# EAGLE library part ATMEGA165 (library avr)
MICROCONTROLLER 16 Kbytes FLASH 1 Kbytes SRAM 512 bytes EEPROM USART 8-channel 10 bit ADC USI
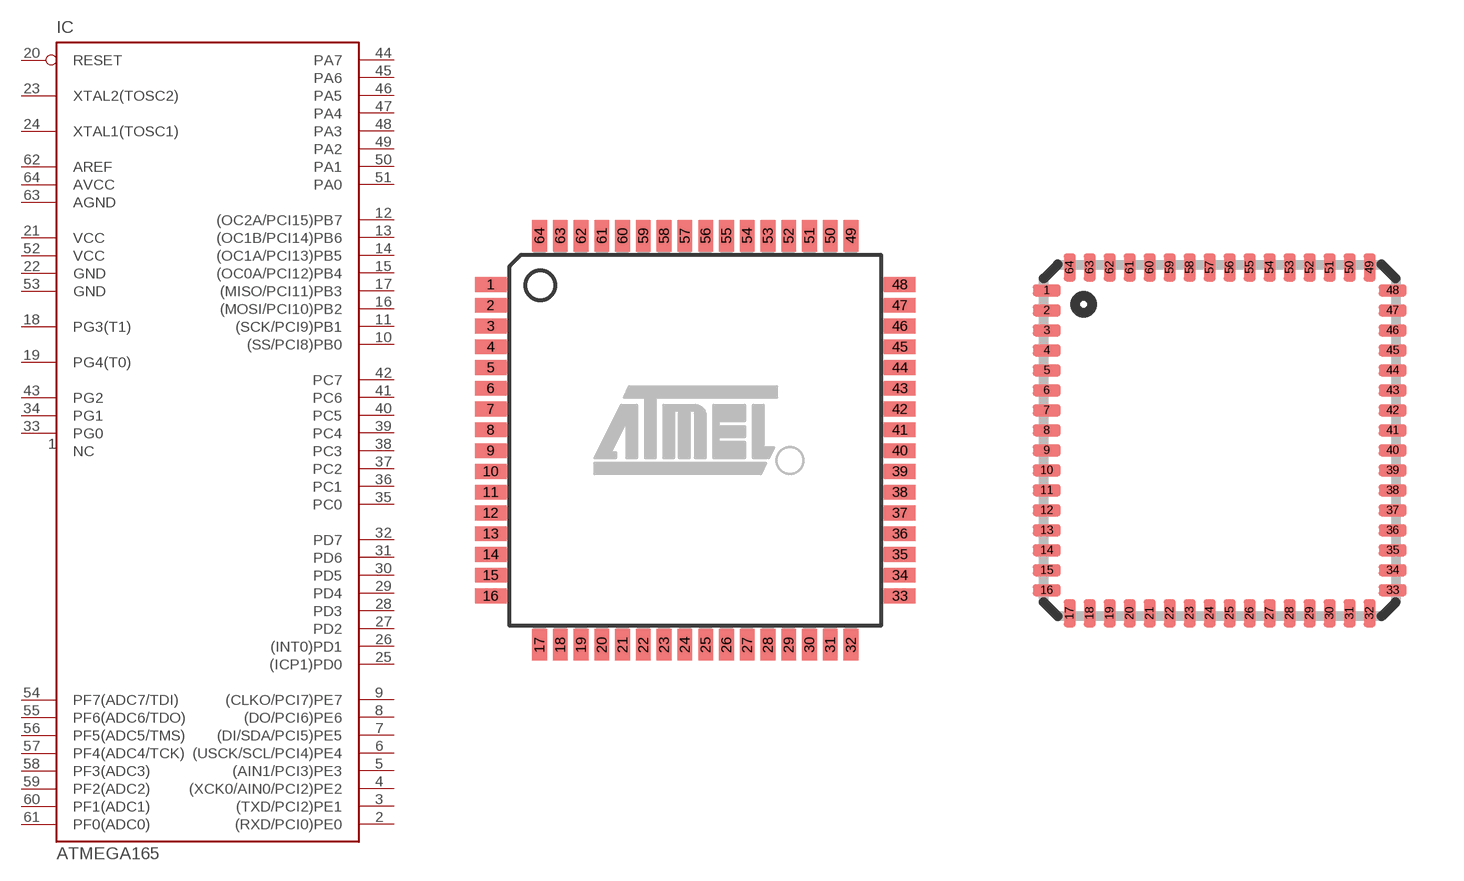
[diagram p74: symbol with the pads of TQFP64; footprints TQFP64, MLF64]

Designator prefix IC

## ATMEGA165-16A, ATMEGA165V-8A  [TQFP64]
1  NC  nc
2  (RXD/PCI0)PE0
3  (TXD/PCI2)PE1
4  (XCK0/AIN0/PCI2)PE2
5  (AIN1/PCI3)PE3
6  (USCK/SCL/PCI4)PE4
7  (DI/SDA/PCI5)PE5
8  (DO/PCI6)PE6
9  (CLKO/PCI7)PE7
10  (SS/PCI8)PB0
11  (SCK/PCI9)PB1
12  (OC2A/PCI15)PB7
13  (OC1B/PCI14)PB6
14  (OC1A/PCI13)PB5
15  (OC0A/PCI12)PB4
16  (MOSI/PCI10)PB2
17  (MISO/PCI11)PB3
18  PG3(T1)
19  PG4(T0)
20  RESET  in
21  VCC  pwr
22  GND  pwr
23  XTAL2(TOSC2)
24  XTAL1(TOSC1)
25  (ICP1)PD0
26  (INT0)PD1
27  PD2
28  PD3
29  PD4
30  PD5
31  PD6
32  PD7
33  PG0
34  PG1
35  PC0
36  PC1
37  PC2
38  PC3
39  PC4
40  PC5
41  PC6
42  PC7
43  PG2
44  PA7
45  PA6
46  PA5
47  PA4
48  PA3
49  PA2
50  PA1
51  PA0
52  VCC  pwr
53  GND  pwr
54  PF7(ADC7/TDI)  in
55  PF6(ADC6/TDO)  in
56  PF5(ADC5/TMS)  in
57  PF4(ADC4/TCK)  in
58  PF3(ADC3)  in
59  PF2(ADC2)  in
60  PF1(ADC1)  in
61  PF0(ADC0)  in
62  AREF  pwr
63  AGND  pwr
64  AVCC  pwr

## ATMEGA165-16M, ATMEGA165V-8M  [MLF64]
Pads as for TQFP64

## Footprint TQFP64 (pad centres in mm)
Thin Plasic Quad Flat Package
smd 1.194 x 0.559: 1 -7.76,5.905; 2 -7.76,5.118; 3 -7.76,4.331; 4 -7.76,3.543; 5 -7.76,2.756; 6 -7.76,1.968; 7 -7.76,1.181; 8 -7.76,0.394; 9 -7.76,-0.394; 10 -7.76,-1.181; 11 -7.76,-1.968; 12 -7.76,-2.756; 13 -7.76,-3.543; 14 -7.76,-4.331; 15 -7.76,-5.118; 16 -7.76,-5.905; 33 7.76,-5.905; 34 7.76,-5.118; 35 7.76,-4.331; 36 7.76,-3.543; 37 7.76,-2.756; 38 7.76,-1.968; 39 7.76,-1.181; 40 7.76,-0.394; 41 7.76,0.394; 42 7.76,1.181; 43 7.76,1.968; 44 7.76,2.756; 45 7.76,3.543; 46 7.76,4.331; 47 7.76,5.118; 48 7.76,5.905
smd 0.559 x 1.194: 17 -5.905,-7.76; 18 -5.118,-7.76; 19 -4.331,-7.76; 20 -3.543,-7.76; 21 -2.756,-7.76; 22 -1.968,-7.76; 23 -1.181,-7.76; 24 -0.394,-7.76; 25 0.394,-7.76; 26 1.181,-7.76; 27 1.968,-7.76; 28 2.756,-7.76; 29 3.543,-7.76; 30 4.331,-7.76; 31 5.118,-7.76; 32 5.905,-7.76; 49 5.905,7.76; 50 5.118,7.76; 51 4.331,7.76; 52 3.543,7.76; 53 2.756,7.76; 54 1.968,7.76; 55 1.181,7.76; 56 0.394,7.76; 57 -0.394,7.76; 58 -1.181,7.76; 59 -1.968,7.76; 60 -2.756,7.76; 61 -3.543,7.76; 62 -4.331,7.76; 63 -5.118,7.76; 64 -5.905,7.76

## Footprint MLF64 (pad centres in mm)
64M1 Micro Lead Frame package (MLF)
smd 0.7 x 0.3: 1 -4.325,3.75; 2 -4.325,3.25; 3 -4.325,2.75; 4 -4.325,2.25; 5 -4.325,1.75; 6 -4.325,1.25; 7 -4.325,0.75; 8 -4.325,0.25; 9 -4.325,-0.25; 10 -4.325,-0.75; 11 -4.325,-1.25; 12 -4.325,-1.75; 13 -4.325,-2.25; 14 -4.325,-2.75; 15 -4.325,-3.25; 16 -4.325,-3.75; 33 4.325,-3.75; 34 4.325,-3.25; 35 4.325,-2.75; 36 4.325,-2.25; 37 4.325,-1.75; 38 4.325,-1.25; 39 4.325,-0.75; 40 4.325,-0.25; 41 4.325,0.25; 42 4.325,0.75; 43 4.325,1.25; 44 4.325,1.75; 45 4.325,2.25; 46 4.325,2.75; 47 4.325,3.25; 48 4.325,3.75
smd 0.3 x 0.7: 17 -3.75,-4.325; 18 -3.25,-4.325; 19 -2.75,-4.325; 20 -2.25,-4.325; 21 -1.75,-4.325; 22 -1.25,-4.325; 23 -0.75,-4.325; 24 -0.25,-4.325; 25 0.25,-4.325; 26 0.75,-4.325; 27 1.25,-4.325; 28 1.75,-4.325; 29 2.25,-4.325; 30 2.75,-4.325; 31 3.25,-4.325; 32 3.75,-4.325; 49 3.75,4.325; 50 3.25,4.325; 51 2.75,4.325; 52 2.25,4.325; 53 1.75,4.325; 54 1.25,4.325; 55 0.75,4.325; 56 0.25,4.325; 57 -0.25,4.325; 58 -0.75,4.325; 59 -1.25,4.325; 60 -1.75,4.325; 61 -2.25,4.325; 62 -2.75,4.325; 63 -3.25,4.325; 64 -3.75,4.325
